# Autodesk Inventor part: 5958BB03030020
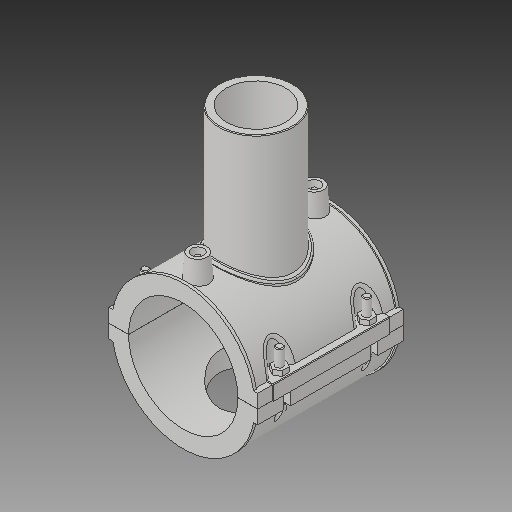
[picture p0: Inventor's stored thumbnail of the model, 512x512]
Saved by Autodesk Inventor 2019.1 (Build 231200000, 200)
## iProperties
Created: 2017-07
Part Number: 5958BB03030020
Material: Generic
Description: PLASSON BRANCH SADDLE 3'' x 2''
Document SubType Name: Modeling
Designer: KIM
Mass: 764.267 g
Surface Area: 1930.38 cm^2
Volume: 764.267 cm^3
Density: 1 g/cm^3
Appearance: Default
Author: KIM
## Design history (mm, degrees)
derived "5958B.ipt"
feature "Solid1::5958B.ipt"
feature "Solid2::5958B.ipt"
feature "Solid3::5958B.ipt"
tag "TaggingFeature1"
body "Solid1"
body "Solid2"
body "Solid3"
other parameters: "d0" = 88.7, "d2" = 120.904, "d3" = 22.175, "d4" = 118.11, "d5" = 0, "d6" = 0.1, "d8" = 0, "d19" = 6, "d20" = 6, "d21" = 70.866, "d23" = 0, "d24" = 35.433, "d26" = 0, "d27" = 3, "d28" = 3, "d29" = 3, "d30" = 29.56667, "d31" = 6, "d32" = 0, "d33" = 0, "d34" = 0.6, "d40" = 59.332, "d41" = 66.11, "d43" = 0, "d45" = 0, "d47" = 153.824, "d48" = 60.1, "d50" = 0, "d70" = 15, "d72" = 0, "d73" = 6, "d75" = 5, "d76" = 0, "d77" = 4.435, "d78" = 74.35, "d79" = 15, "d80" = 47.244, "d82" = 5 deg, "d84" = 4, "d85" = 14, "d86" = 0, "d87" = 3, "d88" = 0, "d89" = 1, "d90" = 1, "d91" = 94.488, "d92" = 0, "d93" = 0.5, "d94" = 46.68421, "d96" = 116.382, "d97" = 2.3622, "d98" = 0, "d102" = 1.803, "d103" = 48.08, "d105" = 0, "d109" = -32.258, "d117" = 0.601, "d120" = 140 deg, "d121" = 24.228, "d122" = 20 deg, "d123" = 228.2, "d124" = 68.46, "d126" = 0, "d143" = 93.135, "d150" = 15.966, "d159" = 5.08, "d161" = 2.2175, "d162" = 70.866, "d163" = 0, "d167" = 17.74, "d168" = 51.86364, "d173" = 1, "d175" = 44.35, "d176" = 20 deg, "d177" = 6.209, "d178" = 25.4, "d180" = 0, "d185" = 38.38575, "d186" = 38.38575, "d187" = 57.05, "d188" = 7.62, "d189" = 6.209, "d190" = 0, "d191" = 85.575, "d200" = 12.7, "d202" = 0, "d216" = 106.299, "d217" = 0, "d221" = 43.7007, "d222" = 6.209, "d223" = 3.7254, "d224" = 44.35, "d225" = 3.7254, "d227" = 12.7728, "d230" = 54.994, "d236" = 11.5 deg, "d238" = 20 deg, "d239" = 6.209, "d240" = 0, "d241" = 0, "d242" = 6.2484, "d_" = 88.7, "B_" = 120.904, "H_" = 96.774, "L_" = 118.11, "d_t" = 6, "d_1" = 60.1, "H_1" = 84.074, "d1" = 114.1, "d148" = 2.2175, "d160" = 2.2175
